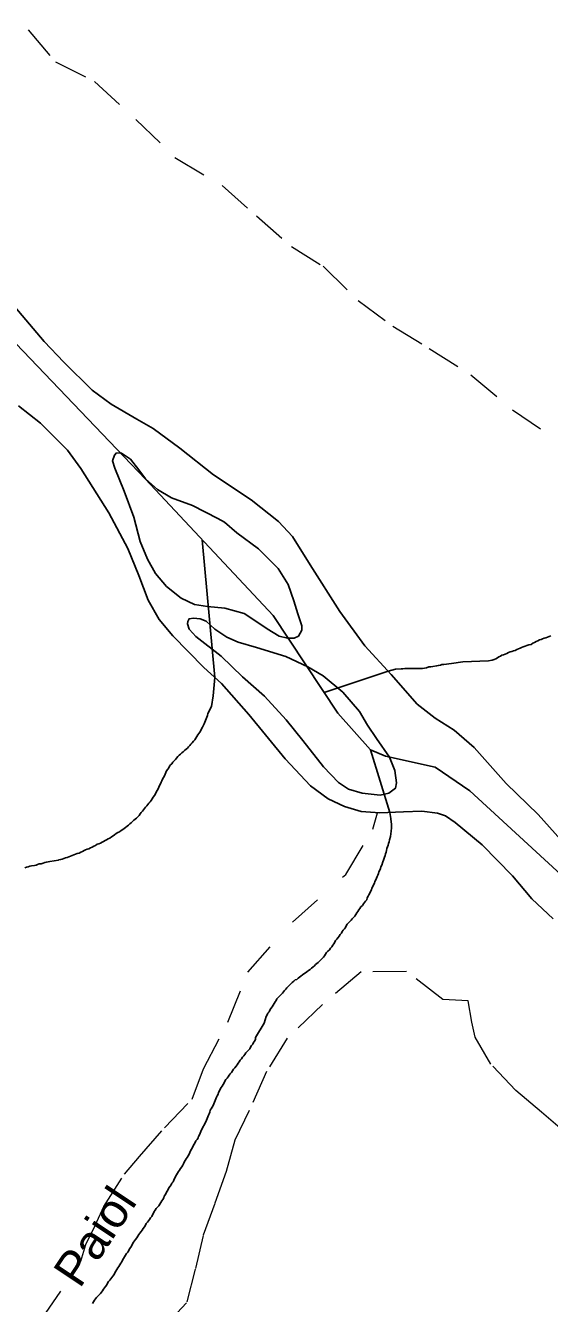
# Model space of a CAD drawing. Extents: x 785.9 to 812.4, y 7674.9 to 7703.1.
# Drawn here: x 789.381 to 790.935, y 7687.529 to 7691.315 of the extents above; entities that cross this region are included whole.
import ezdxf
from ezdxf.enums import TextEntityAlignment as Align

# ---------------------------------------------------------------- set-up
doc = ezdxf.new("R2010")
doc.units = 0
doc.header["$LTSCALE"] = 0.04
doc.linetypes.add('SHORT_DASHED', pattern=[2.7, 1.5, -1.2])
for name, color, linetype, lineweight in [('2', 7, 'Continuous', 25), ('21', 7, 'SHORT_DASHED', 13), ('55', 7, 'Continuous', 25), ('7', 7, 'Continuous', 25)]:
    doc.layers.add(name, color=color, linetype=linetype, lineweight=lineweight)
doc.layers.add('61', color=7, linetype='Continuous')

msp = doc.modelspace()

# ---------------------------------------------------------------- linework, layer by layer
at = {"layer": '2'}
for points in [[(789.3278, 7690.5077), (789.4367, 7690.3795), (789.4948, 7690.3181), (789.5789, 7690.2351), (789.6349, 7690.1931), (789.7114, 7690.1489), (789.7598, 7690.1209), (789.8385, 7690.0627), (789.9387, 7689.9841), (790.0507, 7689.9097), (790.1315, 7689.8461), (790.1735, 7689.8009), (790.2252, 7689.7168), (790.3136, 7689.5789), (790.3879, 7689.4776), (790.4655, 7689.3925), (790.5431, 7689.3041), (790.5958, 7689.2632), (790.6529, 7689.2276), (790.7122, 7689.1759), (790.807, 7689.0692), (790.9018, 7688.9776), (791.003, 7688.8645)], [(789.818, 7689.5069), (789.7772, 7689.5548), (789.7449, 7689.613), (789.7169, 7689.6852), (789.6846, 7689.766), (789.6285, 7689.8716), (789.5456, 7690.0031), (789.5057, 7690.0569), (789.426, 7690.1367), (789.3603, 7690.1884)], [(790.9459, 7688.6685), (790.8824, 7688.7278), (790.8253, 7688.7956), (790.7359, 7688.8872), (790.6551, 7688.954), (790.6271, 7688.9734), (790.6034, 7688.981), (790.557, 7688.9874), (790.5021, 7688.9853), (790.432, 7688.9821), (790.3771, 7688.9864), (790.3275, 7689.0015), (790.2791, 7689.0241), (790.2263, 7689.0629), (790.1509, 7689.1426), (790.0431, 7689.2741), (789.9623, 7689.3657), (789.9096, 7689.4131), (789.818, 7689.5069)]]:
    msp.add_lwpolyline(points, dxfattribs=at)
for points in [[(789.9517, 7689.8544), (789.8763, 7689.8932), (789.8138, 7689.9158), (789.7729, 7689.9406), (789.7374, 7689.9718), (789.7169, 7689.9988), (789.6921, 7690.03), (789.6663, 7690.0483), (789.6512, 7690.0494), (789.6447, 7690.0419), (789.6393, 7690.0257), (789.6458, 7690.0041), (789.6738, 7689.9352), (789.7029, 7689.8587), (789.7212, 7689.7865), (789.7427, 7689.7337), (789.7664, 7689.6916), (789.7998, 7689.6529), (789.8429, 7689.6184), (789.8828, 7689.6001), (789.9205, 7689.5936), (789.9722, 7689.5893), (790.0293, 7689.5731), (790.0616, 7689.5526), (790.0982, 7689.5279), (790.1338, 7689.5063), (790.1586, 7689.4998), (790.178, 7689.4998), (790.1909, 7689.5063), (790.2006, 7689.5236), (790.2006, 7689.5365), (790.1887, 7689.572), (790.1769, 7689.6108), (790.1597, 7689.6593), (790.1306, 7689.7067), (790.0724, 7689.7649), (790.0078, 7689.8123), (789.9711, 7689.8436)], [(789.8859, 7689.5047), (789.9613, 7689.4465), (790.0248, 7689.3851), (790.0895, 7689.328), (790.1541, 7689.2579), (790.2037, 7689.1965), (790.2651, 7689.1189), (790.3092, 7689.0726), (790.3394, 7689.0521), (790.3793, 7689.0403), (790.4331, 7689.0349), (790.459, 7689.0403), (790.4784, 7689.0554), (790.4816, 7689.0715), (790.4762, 7689.1082), (790.4611, 7689.147), (790.4224, 7689.203), (790.3954, 7689.2418), (790.3717, 7689.2827), (790.3222, 7689.3398), (790.264, 7689.3883), (790.2187, 7689.4153), (790.153, 7689.4454), (790.0658, 7689.4724), (790.0119, 7689.4885), (789.9785, 7689.5025), (789.943, 7689.5263), (789.9171, 7689.55), (789.8988, 7689.5575), (789.8794, 7689.5597), (789.8665, 7689.5575), (789.8622, 7689.5489), (789.8611, 7689.5424), (789.8665, 7689.5263), (789.8772, 7689.5144)]]:
    msp.add_lwpolyline(points, close=True, dxfattribs=at)
at = {"layer": '21'}
for points in [[(789.2556, 7691.2946), (789.3886, 7691.3026), (789.4698, 7691.2076), (789.5861, 7691.1495), (789.7082, 7691.037), (789.8245, 7690.9245), (789.9648, 7690.841), (790.0659, 7690.751), (790.1699, 7690.6602), (790.2638, 7690.6022), (790.3678, 7690.5006), (790.4711, 7690.4244), (790.5787, 7690.3583), (790.7023, 7690.28), (790.8259, 7690.1762), (790.9589, 7690.0862)], [(789.4292, 7687.4826), (789.5164, 7687.6085), (789.5448, 7687.6542), (789.5597, 7687.7037), (789.5881, 7687.7593), (789.6133, 7687.8157), (789.6746, 7687.9113), (789.7197, 7687.9645), (789.7935, 7688.0492), (789.8753, 7688.1339), (789.909, 7688.2243), (789.9816, 7688.3617), (790.0405, 7688.5105), (790.1726, 7688.6582), (790.331, 7688.8001), (790.4116, 7688.934), (790.425, 7688.9826)], [(790.9879, 7688.0306), (790.9118, 7688.0951), (790.8357, 7688.1596), (790.7616, 7688.2374), (790.7148, 7688.3172), (790.7052, 7688.3625), (790.6942, 7688.4256), (790.6188, 7688.429), (790.5109, 7688.5127), (790.3764, 7688.5114), (790.2618, 7688.4144), (790.1572, 7688.3146), (790.0958, 7688.2156), (790.0443, 7688.0999), (790.0021, 7688.0121), (789.9765, 7687.9196), (789.9423, 7687.8246), (789.9081, 7687.7295), (789.8845, 7687.6304), (789.8589, 7687.5306), (789.7676, 7687.4329)]]:
    msp.add_lwpolyline(points, dxfattribs=at)
at = {"layer": '55'}
for p, q in [((789.9426, 7689.3834), (789.9053, 7689.7914)), ((790.4567, 7689.4021), (790.2673, 7689.339)), ((790.4615, 7688.9834), (790.4039, 7689.1692))]:
    msp.add_line(p, q, dxfattribs=at)
for points in [[(787.2059, 7693.3555), (787.0046, 7693.1062), (786.8705, 7692.8732), (786.873, 7692.6563), (786.9051, 7692.4703), (786.9435, 7692.297), (786.9948, 7692.1174), (787.0846, 7691.9955), (787.3218, 7691.8158), (787.6617, 7691.5913), (787.8091, 7691.4822), (787.9053, 7691.386), (788.0207, 7691.2897), (788.2965, 7691.2641), (788.5016, 7691.1742), (788.9184, 7690.7636), (789.3095, 7690.4171), (789.7371, 7689.9712), (790.1154, 7689.567), (790.3077, 7689.2782), (790.4039, 7689.1692)], [(790.4039, 7689.1692), (790.4488, 7689.1499), (790.5963, 7689.1178), (790.6989, 7689.0473), (791.1541, 7688.6302), (791.2631, 7688.5596), (791.6414, 7688.3158), (792.1672, 7687.9694), (792.2954, 7687.8988), (792.4044, 7687.886), (792.5006, 7687.8796), (792.6096, 7687.8796), (792.7058, 7687.8924), (793.1033, 7687.8988), (793.2508, 7687.9052), (793.3406, 7687.8796), (793.4239, 7687.8475)]]:
    msp.add_lwpolyline(points, dxfattribs=at)
at = {"layer": '7'}
for points in [[(790.9392, 7689.5068), (790.9343, 7689.5052), (790.9295, 7689.5028), (790.9246, 7689.5012), (790.9198, 7689.4995), (790.9149, 7689.4979), (790.9101, 7689.4963), (790.9052, 7689.4947), (790.9004, 7689.4923), (790.8955, 7689.4898), (790.8907, 7689.4874), (790.8858, 7689.485), (790.8809, 7689.4817), (790.8737, 7689.4801), (790.868, 7689.4785), (790.8631, 7689.4761), (790.8575, 7689.4745), (790.8526, 7689.472), (790.8478, 7689.4704), (790.8429, 7689.4688), (790.8381, 7689.4664), (790.8332, 7689.4639), (790.8283, 7689.4623), (790.8235, 7689.4607), (790.8186, 7689.4591), (790.8138, 7689.4575), (790.8089, 7689.455), (790.8041, 7689.4526), (790.7992, 7689.451), (790.7944, 7689.4494), (790.7895, 7689.4469), (790.7847, 7689.4445), (790.7806, 7689.4413), (790.7758, 7689.4389), (790.7709, 7689.4364), (790.7652, 7689.4348), (790.7539, 7689.4332), (790.6783, 7689.4299)], [(790.6783, 7689.4299), (790.6447, 7689.4251), (790.622, 7689.4219), (790.6164, 7689.4219), (790.6115, 7689.4202), (790.6058, 7689.4194), (790.6002, 7689.4178), (790.5888, 7689.4162), (790.5832, 7689.4154), (790.5775, 7689.4146), (790.5702, 7689.4121), (790.5646, 7689.4113), (790.5589, 7689.4105), (790.5419, 7689.4105), (790.5362, 7689.4097), (790.5306, 7689.4097), (790.516, 7689.4105), (790.5063, 7689.4097), (790.5006, 7689.4089), (790.495, 7689.4089), (790.479, 7689.4078), (790.4567, 7689.4021)], [(789.9426, 7689.3834), (789.9379, 7689.3294), (789.9324, 7689.2974), (789.9219, 7689.277), (789.9208, 7689.2709), (789.9107, 7689.246), (789.9058, 7689.2363), (789.9034, 7689.2314), (789.901, 7689.2266), (789.8986, 7689.2217), (789.8953, 7689.2177), (789.8921, 7689.2136), (789.8888, 7689.2088), (789.8864, 7689.2039), (789.8832, 7689.1991), (789.8791, 7689.195), (789.8759, 7689.1902), (789.8718, 7689.1861), (789.8686, 7689.1821), (789.8646, 7689.178), (789.8613, 7689.174), (789.8573, 7689.1707), (789.8524, 7689.1675), (789.8492, 7689.1635), (789.8451, 7689.1602), (789.8411, 7689.1562), (789.8371, 7689.1529), (789.833, 7689.1489), (789.829, 7689.1448), (789.8257, 7689.1408), (789.8225, 7689.1368), (789.8184, 7689.1327), (789.8152, 7689.1279), (789.8112, 7689.1246), (789.8079, 7689.1206), (789.8063, 7689.1157), (789.8031, 7689.1117), (789.7998, 7689.1068), (789.7974, 7689.102), (789.795, 7689.0971), (789.7934, 7689.0923), (789.7909, 7689.0874), (789.7877, 7689.0825), (789.7853, 7689.0777), (789.7837, 7689.0728), (789.7812, 7689.068), (789.7788, 7689.0631), (789.7764, 7689.0583), (789.7748, 7689.0534), (789.7715, 7689.0486), (789.7691, 7689.0437), (789.7667, 7689.0389), (789.7634, 7689.034), (789.7602, 7689.0291), (789.757, 7689.0243), (789.7537, 7689.0194), (789.7505, 7689.0154), (789.7472, 7689.0113), (789.744, 7689.0073), (789.7408, 7689.0032), (789.7375, 7688.9992), (789.7343, 7688.9952), (789.7311, 7688.9911), (789.7278, 7688.9871), (789.7246, 7688.983), (789.7213, 7688.979), (789.7181, 7688.9741), (789.7141, 7688.9709), (789.7108, 7688.9668), (789.7068, 7688.9636), (789.7027, 7688.9604), (789.6987, 7688.9571), (789.6946, 7688.9531), (789.6906, 7688.9498), (789.6866, 7688.9458), (789.6825, 7688.9426), (789.6777, 7688.9393), (789.6736, 7688.9361), (789.6696, 7688.9329), (789.6647, 7688.9296), (789.6599, 7688.9264), (789.655, 7688.924), (789.6501, 7688.9207), (789.6453, 7688.9175), (789.6412, 7688.9142), (789.6364, 7688.911), (789.6315, 7688.9078), (789.6267, 7688.9053), (789.6218, 7688.9021), (789.617, 7688.9005), (789.6129, 7688.8973), (789.6081, 7688.8956), (789.6032, 7688.8924), (789.5984, 7688.8908), (789.5935, 7688.8892), (789.5886, 7688.8859), (789.5838, 7688.8835), (789.5789, 7688.8811), (789.5741, 7688.8786), (789.5692, 7688.8762), (789.5644, 7688.8746)], [(790.4615, 7688.9834), (790.4643, 7688.9656), (790.466, 7688.9551), (790.4668, 7688.9494), (790.4668, 7688.9381), (790.466, 7688.9276), (790.4635, 7688.9122), (790.4603, 7688.9025), (790.4595, 7688.8968), (790.4579, 7688.892), (790.4563, 7688.8863), (790.4546, 7688.8815), (790.453, 7688.8766), (790.4522, 7688.8709), (790.4506, 7688.8661), (790.449, 7688.8612), (790.4474, 7688.8564), (790.4457, 7688.8515), (790.4425, 7688.8418), (790.4409, 7688.8369)], [(789.5644, 7688.8746), (789.5595, 7688.873), (789.5547, 7688.8706), (789.5498, 7688.8681), (789.545, 7688.8657), (789.5401, 7688.8633), (789.5344, 7688.8616), (789.5296, 7688.86), (789.5247, 7688.8584), (789.5199, 7688.856), (789.5142, 7688.8544), (789.5094, 7688.8519), (789.5045, 7688.8503), (789.4996, 7688.8487), (789.4948, 7688.8471), (789.4899, 7688.8455), (789.4851, 7688.8438), (789.4794, 7688.843), (789.4794, 7688.8422), (789.4535, 7688.8382), (789.443, 7688.8366), (789.4381, 7688.8349), (789.4333, 7688.8333), (789.4276, 7688.8317), (789.422, 7688.8309), (789.4171, 7688.8293), (789.4123, 7688.8277), (789.4074, 7688.826), (789.3993, 7688.8252), (789.3936, 7688.8244), (789.3888, 7688.8228), (789.3839, 7688.8212), (789.3791, 7688.8196)], [(790.4409, 7688.8369), (790.4376, 7688.8272), (790.4352, 7688.8224), (790.4336, 7688.8175), (790.432, 7688.8127), (790.4295, 7688.8078), (790.4279, 7688.803), (790.4263, 7688.7981), (790.4239, 7688.7933), (790.4223, 7688.7884), (790.4198, 7688.7835), (790.4174, 7688.7787), (790.4158, 7688.7738), (790.4134, 7688.769), (790.4109, 7688.7641), (790.4085, 7688.7593), (790.4069, 7688.7544), (790.4045, 7688.7496), (790.402, 7688.7447), (790.3996, 7688.7399), (790.3972, 7688.735), (790.3948, 7688.7301), (790.3931, 7688.7245), (790.3899, 7688.7204), (790.3867, 7688.7164), (790.3834, 7688.7123), (790.3802, 7688.7075), (790.3761, 7688.7034), (790.3729, 7688.6986), (790.3697, 7688.6945), (790.3672, 7688.6897), (790.364, 7688.6856), (790.3608, 7688.6816), (790.3575, 7688.6767), (790.3535, 7688.6727), (790.3503, 7688.6686), (790.347, 7688.6646), (790.3389, 7688.6565), (790.3349, 7688.6525), (790.3325, 7688.6476), (790.33, 7688.6428), (790.3268, 7688.6387), (790.3236, 7688.6347), (790.3203, 7688.6306), (790.3179, 7688.6258), (790.3147, 7688.6217), (790.3114, 7688.6169), (790.3082, 7688.6128), (790.3049, 7688.608), (790.3009, 7688.6039), (790.2985, 7688.5991), (790.296, 7688.5942), (790.2928, 7688.5902), (790.2896, 7688.5853), (790.2855, 7688.5813), (790.2823, 7688.5764), (790.2782, 7688.5724), (790.2742, 7688.5683), (790.2677, 7688.5586), (790.2645, 7688.5546), (790.2612, 7688.5505), (790.2572, 7688.5465), (790.2532, 7688.5424), (790.2491, 7688.5392), (790.2451, 7688.5359), (790.241, 7688.5327), (790.2378, 7688.5287), (790.2337, 7688.5254), (790.2297, 7688.5222), (790.2256, 7688.5181), (790.2208, 7688.5149), (790.2159, 7688.5117), (790.2119, 7688.5084), (790.207, 7688.5052), (790.2022, 7688.502), (790.1981, 7688.4987), (790.1941, 7688.4955), (790.19, 7688.4923), (790.186, 7688.489), (790.1811, 7688.4874), (790.1771, 7688.4834), (790.1722, 7688.4801), (790.1682, 7688.4761), (790.1561, 7688.4639), (790.1528, 7688.4599), (790.1496, 7688.4558), (790.1431, 7688.4477), (790.1391, 7688.4437), (790.135, 7688.4397), (790.131, 7688.4356), (790.1269, 7688.4316), (790.1245, 7688.4267), (790.1221, 7688.4219), (790.1124, 7688.4073), (790.1091, 7688.4024), (790.1059, 7688.3976), (790.1035, 7688.3927), (790.1002, 7688.3887), (790.0978, 7688.3838), (790.0946, 7688.379), (790.0889, 7688.3596)], [(790.0889, 7688.3596), (790.063, 7688.3167), (790.063, 7688.311), (790.0606, 7688.3061), (790.0573, 7688.3021), (790.0549, 7688.2972), (790.0517, 7688.2932), (790.0484, 7688.2883), (790.046, 7688.2835), (790.0428, 7688.2794), (790.0387, 7688.2754), (790.0347, 7688.2714), (790.0315, 7688.2665), (790.0282, 7688.2625), (790.025, 7688.2584), (790.0217, 7688.2536), (790.0177, 7688.2495), (790.0153, 7688.2447), (790.012, 7688.2406), (790.0088, 7688.2358), (790.0056, 7688.2317), (790.0023, 7688.2269), (789.9983, 7688.2228), (789.995, 7688.218), (789.9918, 7688.2131), (789.9886, 7688.2091), (789.9853, 7688.205), (789.9821, 7688.2002), (789.9789, 7688.1961), (789.9756, 7688.1921), (789.9724, 7688.1872), (789.97, 7688.1824), (789.9675, 7688.1775), (789.9643, 7688.1726), (789.9611, 7688.1686), (789.9586, 7688.1637), (789.9562, 7688.1589), (789.9538, 7688.154), (789.9522, 7688.1492), (789.9497, 7688.1443), (789.9481, 7688.1395), (789.9457, 7688.1346), (789.9433, 7688.1298), (789.9416, 7688.1249), (789.94, 7688.12), (789.9376, 7688.1152), (789.9352, 7688.1103), (789.9319, 7688.1055), (789.9287, 7688.1014), (789.9279, 7688.0958), (789.9263, 7688.0909), (789.9238, 7688.0861), (789.9222, 7688.0812), (789.9198, 7688.0764), (789.9182, 7688.0715), (789.9157, 7688.0666), (789.9133, 7688.0618), (789.9109, 7688.0569), (789.9077, 7688.0529), (789.906, 7688.048), (789.9036, 7688.0432), (789.9012, 7688.0383), (789.8996, 7688.0335), (789.8971, 7688.0286), (789.8947, 7688.0238), (789.8931, 7688.0189), (789.8899, 7688.0149), (789.8866, 7688.01), (789.8842, 7688.0051), (789.8818, 7688.0003), (789.8785, 7687.9954), (789.8761, 7687.9906), (789.8737, 7687.9857), (789.8704, 7687.9809), (789.8688, 7687.976), (789.8664, 7687.9712), (789.864, 7687.9663), (789.8607, 7687.9615), (789.8575, 7687.9574), (789.8542, 7687.9526), (789.8518, 7687.9477), (789.8494, 7687.9428), (789.8478, 7687.938), (789.8445, 7687.9331), (789.8413, 7687.9283), (789.8381, 7687.9234), (789.8348, 7687.9194), (789.8324, 7687.9145), (789.8292, 7687.9097), (789.8259, 7687.9048), (789.8211, 7687.8943), (789.8186, 7687.8894), (789.8154, 7687.8846), (789.813, 7687.8797), (789.8097, 7687.8757), (789.8065, 7687.8708), (789.8041, 7687.866), (789.8017, 7687.8611), (789.7984, 7687.8563), (789.796, 7687.8514), (789.7928, 7687.8466)], [(789.7928, 7687.8466), (789.7911, 7687.8417), (789.7887, 7687.8368), (789.7855, 7687.8328), (789.7822, 7687.8279), (789.7798, 7687.8231), (789.7766, 7687.8182), (789.7725, 7687.8142), (789.7685, 7687.8101), (789.7661, 7687.8053), (789.7628, 7687.8012), (789.7612, 7687.7964), (789.758, 7687.7915), (789.7555, 7687.7867), (789.7523, 7687.7826), (789.7491, 7687.7778), (789.7458, 7687.7737), (789.7426, 7687.7697), (789.7393, 7687.7656), (789.7369, 7687.7608), (789.7337, 7687.7559), (789.7304, 7687.7511), (789.7272, 7687.7462), (789.724, 7687.7422), (789.7207, 7687.7373), (789.7175, 7687.7325), (789.7143, 7687.7276), (789.711, 7687.7228), (789.7078, 7687.7179), (789.7046, 7687.7139), (789.7013, 7687.7098), (789.6981, 7687.705), (789.6965, 7687.7001), (789.6932, 7687.6952), (789.69, 7687.6904), (789.6876, 7687.6855), (789.6851, 7687.6807), (789.6811, 7687.6766), (789.6779, 7687.6718), (789.6746, 7687.6669), (789.6714, 7687.6621), (789.669, 7687.6572), (789.6665, 7687.6524), (789.6641, 7687.6475), (789.6609, 7687.6427), (789.6584, 7687.6378), (789.6552, 7687.6338), (789.652, 7687.6289), (789.6487, 7687.624), (789.6463, 7687.6192), (789.6439, 7687.6143), (789.6406, 7687.6095), (789.6374, 7687.6054), (789.6342, 7687.6014), (789.6309, 7687.5973), (789.6277, 7687.5933), (789.6245, 7687.5884), (789.622, 7687.5836), (789.6188, 7687.5787), (789.6156, 7687.5747), (789.6123, 7687.5706), (789.6099, 7687.5658), (789.6067, 7687.5617), (789.6034, 7687.5577), (789.5994, 7687.5545), (789.5953, 7687.5504), (789.5921, 7687.5464), (789.5888, 7687.5423), (789.5856, 7687.5383), (789.5824, 7687.5334), (789.5799, 7687.5286)]]:
    msp.add_lwpolyline(points, dxfattribs=at)

# ---------------------------------------------------------------- texts
at = {"layer": '61', "width": 1.05}
msp.add_text('Paiol', height=0.1, rotation=56.324, dxfattribs=at).set_placement((789.6283, 7687.6999), align=Align.CENTER)

doc.saveas('drawing.dxf')
